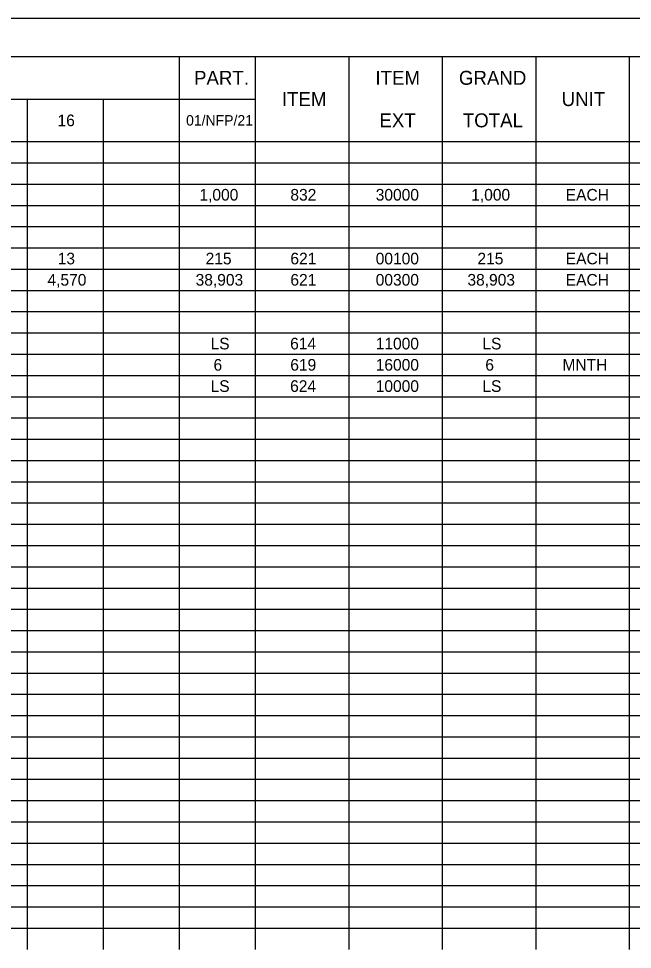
# Model space of a CAD drawing. Extents: x 0 to 34, y 0 to 22.
# Drawn here: x 8.4 to 16.49, y 9.74 to 22 of the extents above; entities that cross this region are included whole.
import ezdxf

# ---------------------------------------------------------------- set-up
doc = ezdxf.new("R2010")
doc.units = 0
for name, color, linetype in [('SH_Border', 7, 'Continuous'), ('SH_Cut_Line', 7, 'Continuous'), ('SH_Text', 7, 'Continuous')]:
    doc.layers.add(name, color=color, linetype=linetype)

msp = doc.modelspace()

# ---------------------------------------------------------------- linework, layer by layer
at = {"layer": 'SH_Border'}
msp.add_lwpolyline([(1.5, 21.5), (33.5, 21.5), (33.5, 0.5), (1.5, 0.5)], close=True, dxfattribs=at)
at = {"layer": 'SH_Cut_Line'}
msp.add_lwpolyline([(0, 0), (34, 0), (34, 22), (0, 22)], close=True, dxfattribs=at)
at = {"layer": 'SH_Text'}
for p, q in [((7.51, 21.5), (13.983, 21.5)), ((10.515, 21.5), (10.515, 21.22)), ((11.517, 21.5), (11.517, 21.22)), ((12.75, 21.5), (12.75, 21.22)), ((13.983, 21.5), (16.448, 21.5)), ((13.983, 21.5), (13.983, 21.22)), ((15.215, 21.5), (15.215, 21.22)), ((16.448, 21.5), (32, 21.5)), ((16.448, 21.5), (16.448, 21.22)), ((10.515, 21.22), (10.515, 20.94)), ((11.517, 21.22), (11.517, 20.94)), ((12.75, 21.22), (12.75, 20.94)), ((13.983, 21.22), (13.983, 20.94)), ((15.215, 21.22), (15.215, 20.94)), ((16.448, 21.22), (16.448, 20.94)), ((7.51, 20.94), (11.517, 20.94)), ((8.512, 20.94), (8.512, 20.66)), ((9.513, 20.94), (9.513, 20.66)), ((10.515, 20.94), (10.515, 20.66)), ((11.517, 20.94), (11.517, 20.66)), ((12.75, 20.94), (12.75, 20.66)), ((13.983, 20.94), (13.983, 20.66)), ((15.215, 20.94), (15.215, 20.66)), ((16.448, 20.94), (16.448, 20.66)), ((8.512, 20.66), (8.512, 20.38)), ((9.513, 20.66), (9.513, 20.38)), ((10.515, 20.66), (10.515, 20.38)), ((11.517, 20.66), (11.517, 20.38)), ((12.75, 20.66), (12.75, 20.38)), ((13.983, 20.66), (13.983, 20.38)), ((15.215, 20.66), (15.215, 20.38)), ((16.448, 20.66), (16.448, 20.38)), ((7.51, 20.38), (13.983, 20.38)), ((8.512, 20.38), (8.512, 20.1)), ((9.513, 20.38), (9.513, 20.1)), ((10.515, 20.38), (10.515, 20.1)), ((11.517, 20.38), (11.517, 20.1)), ((12.75, 20.38), (12.75, 20.1)), ((13.983, 20.38), (16.448, 20.38)), ((13.983, 20.38), (13.983, 20.1)), ((15.215, 20.38), (15.215, 20.1)), ((16.448, 20.38), (32, 20.38)), ((16.448, 20.38), (16.448, 20.1)), ((7.51, 20.1), (13.983, 20.1)), ((8.512, 20.1), (8.512, 18.7)), ((9.513, 20.1), (9.513, 18.7)), ((10.515, 20.1), (10.515, 18.7)), ((11.517, 20.1), (11.517, 18.7)), ((12.75, 20.1), (12.75, 18.7)), ((13.983, 20.1), (16.448, 20.1)), ((13.983, 20.1), (13.983, 18.7)), ((15.215, 20.1), (15.215, 18.7)), ((16.448, 20.1), (32, 20.1)), ((16.448, 20.1), (16.448, 18.7)), ((7.51, 19.82), (13.983, 19.82)), ((13.983, 19.82), (16.448, 19.82)), ((16.448, 19.82), (32, 19.82)), ((7.51, 19.54), (13.983, 19.54)), ((13.983, 19.54), (16.448, 19.54)), ((16.448, 19.54), (32, 19.54)), ((7.51, 19.26), (13.983, 19.26)), ((13.983, 19.26), (16.448, 19.26)), ((16.448, 19.26), (32, 19.26)), ((7.51, 18.98), (13.983, 18.98)), ((13.983, 18.98), (16.448, 18.98)), ((16.448, 18.98), (32, 18.98)), ((7.51, 18.7), (13.983, 18.7)), ((8.512, 18.7), (8.512, 18.14)), ((9.513, 18.7), (9.513, 18.14)), ((10.515, 18.7), (10.515, 18.14)), ((11.517, 18.7), (11.517, 18.14)), ((12.75, 18.7), (12.75, 18.14)), ((13.983, 18.7), (16.448, 18.7)), ((13.983, 18.7), (13.983, 18.14)), ((15.215, 18.7), (15.215, 18.14)), ((16.448, 18.7), (32, 18.7)), ((16.448, 18.7), (16.448, 18.14)), ((7.51, 18.42), (13.983, 18.42)), ((13.983, 18.42), (16.448, 18.42)), ((16.448, 18.42), (32, 18.42)), ((7.51, 18.14), (13.983, 18.14)), ((8.512, 18.14), (8.512, 17.86)), ((9.513, 18.14), (9.513, 17.86)), ((10.515, 18.14), (10.515, 17.86)), ((11.517, 18.14), (11.517, 17.86)), ((12.75, 18.14), (12.75, 17.86)), ((13.983, 18.14), (16.448, 18.14)), ((13.983, 18.14), (13.983, 17.86)), ((15.215, 18.14), (15.215, 17.86)), ((16.448, 18.14), (32, 18.14)), ((16.448, 18.14), (16.448, 17.86)), ((7.51, 17.86), (13.983, 17.86)), ((8.512, 17.86), (8.512, 17.58)), ((9.513, 17.86), (9.513, 17.58)), ((10.515, 17.86), (10.515, 17.58)), ((11.517, 17.86), (11.517, 17.58)), ((12.75, 17.86), (12.75, 17.58)), ((13.983, 17.86), (16.448, 17.86)), ((13.983, 17.86), (13.983, 17.58)), ((15.215, 17.86), (15.215, 17.58)), ((16.448, 17.86), (32, 17.86)), ((16.448, 17.86), (16.448, 17.58)), ((7.51, 17.58), (13.983, 17.58)), ((8.512, 17.58), (8.512, 17.3)), ((9.513, 17.58), (9.513, 17.3)), ((10.515, 17.58), (10.515, 17.3)), ((11.517, 17.58), (11.517, 17.3)), ((12.75, 17.58), (12.75, 17.3)), ((13.983, 17.58), (16.448, 17.58)), ((13.983, 17.58), (13.983, 17.3)), ((15.215, 17.58), (15.215, 17.3)), ((16.448, 17.58), (32, 17.58)), ((16.448, 17.58), (16.448, 17.3)), ((7.51, 17.3), (13.983, 17.3)), ((8.512, 17.3), (8.512, 17.02)), ((9.513, 17.3), (9.513, 17.02)), ((10.515, 17.3), (10.515, 17.02)), ((11.517, 17.3), (11.517, 17.02)), ((12.75, 17.3), (12.75, 17.02)), ((13.983, 17.3), (16.448, 17.3)), ((13.983, 17.3), (13.983, 17.02)), ((15.215, 17.3), (15.215, 17.02)), ((16.448, 17.3), (32, 17.3)), ((16.448, 17.3), (16.448, 17.02)), ((7.51, 17.02), (13.983, 17.02)), ((8.512, 17.02), (8.512, 16.74)), ((9.513, 17.02), (9.513, 16.74)), ((10.515, 17.02), (10.515, 16.74)), ((11.517, 17.02), (11.517, 16.74)), ((12.75, 17.02), (12.75, 16.74)), ((13.983, 17.02), (16.448, 17.02)), ((13.983, 17.02), (13.983, 16.74)), ((15.215, 17.02), (15.215, 16.74)), ((16.448, 17.02), (32, 17.02)), ((16.448, 17.02), (16.448, 16.74)), ((7.51, 16.74), (13.983, 16.74)), ((8.512, 16.74), (8.512, 16.18)), ((9.513, 16.74), (9.513, 16.18)), ((10.515, 16.74), (10.515, 16.18)), ((11.517, 16.74), (11.517, 16.18)), ((12.75, 16.74), (12.75, 16.18)), ((13.983, 16.74), (16.448, 16.74)), ((13.983, 16.74), (13.983, 16.18)), ((15.215, 16.74), (15.215, 16.18)), ((16.448, 16.74), (32, 16.74)), ((16.448, 16.74), (16.448, 16.18)), ((7.51, 16.46), (13.983, 16.46)), ((13.983, 16.46), (16.448, 16.46)), ((16.448, 16.46), (32, 16.46)), ((7.51, 16.18), (13.983, 16.18)), ((8.512, 16.18), (8.512, 15.9)), ((9.513, 16.18), (9.513, 15.9)), ((10.515, 16.18), (10.515, 15.9)), ((11.517, 16.18), (11.517, 15.9)), ((12.75, 16.18), (12.75, 15.9)), ((13.983, 16.18), (16.448, 16.18)), ((13.983, 16.18), (13.983, 15.9)), ((15.215, 16.18), (15.215, 15.9)), ((16.448, 16.18), (32, 16.18)), ((16.448, 16.18), (16.448, 15.9)), ((7.51, 15.9), (13.983, 15.9)), ((8.512, 15.9), (8.512, 15.62)), ((9.513, 15.9), (9.513, 15.62)), ((10.515, 15.9), (10.515, 15.62)), ((11.517, 15.9), (11.517, 15.62)), ((12.75, 15.9), (12.75, 15.62)), ((13.983, 15.9), (16.448, 15.9)), ((13.983, 15.9), (13.983, 15.62)), ((15.215, 15.9), (15.215, 15.62)), ((16.448, 15.9), (32, 15.9)), ((16.448, 15.9), (16.448, 15.62)), ((7.51, 15.62), (13.983, 15.62)), ((8.512, 15.62), (8.512, 15.34)), ((9.513, 15.62), (9.513, 15.34)), ((10.515, 15.62), (10.515, 15.34)), ((11.517, 15.62), (11.517, 15.34)), ((12.75, 15.62), (12.75, 15.34)), ((13.983, 15.62), (16.448, 15.62)), ((13.983, 15.62), (13.983, 15.34)), ((15.215, 15.62), (15.215, 15.34)), ((16.448, 15.62), (32, 15.62)), ((16.448, 15.62), (16.448, 15.34)), ((7.51, 15.34), (13.983, 15.34)), ((8.512, 15.34), (8.512, 14.78)), ((9.513, 15.34), (9.513, 14.78)), ((10.515, 15.34), (10.515, 14.78)), ((11.517, 15.34), (11.517, 14.78)), ((12.75, 15.34), (12.75, 14.78)), ((13.983, 15.34), (16.448, 15.34)), ((13.983, 15.34), (13.983, 14.78)), ((15.215, 15.34), (15.215, 14.78)), ((16.448, 15.34), (32, 15.34)), ((16.448, 15.34), (16.448, 14.78)), ((7.51, 15.06), (13.983, 15.06)), ((13.983, 15.06), (16.448, 15.06)), ((16.448, 15.06), (32, 15.06)), ((7.51, 14.78), (13.983, 14.78)), ((8.512, 14.78), (8.512, 14.5)), ((9.513, 14.78), (9.513, 14.5)), ((10.515, 14.78), (10.515, 14.5)), ((11.517, 14.78), (11.517, 14.5)), ((12.75, 14.78), (12.75, 14.5)), ((13.983, 14.78), (16.448, 14.78)), ((13.983, 14.78), (13.983, 14.5)), ((15.215, 14.78), (15.215, 14.5)), ((16.448, 14.78), (32, 14.78)), ((16.448, 14.78), (16.448, 14.5)), ((7.51, 14.5), (13.983, 14.5)), ((8.512, 14.5), (8.512, 14.22)), ((9.513, 14.5), (9.513, 14.22)), ((10.515, 14.5), (10.515, 14.22)), ((11.517, 14.5), (11.517, 14.22)), ((12.75, 14.5), (12.75, 14.22)), ((13.983, 14.5), (16.448, 14.5)), ((13.983, 14.5), (13.983, 14.22)), ((15.215, 14.5), (15.215, 14.22)), ((16.448, 14.5), (32, 14.5)), ((16.448, 14.5), (16.448, 14.22)), ((7.51, 14.22), (13.983, 14.22)), ((8.512, 14.22), (8.512, 13.94)), ((9.513, 14.22), (9.513, 13.94)), ((10.515, 14.22), (10.515, 13.94)), ((11.517, 14.22), (11.517, 13.94)), ((12.75, 14.22), (12.75, 13.94)), ((13.983, 14.22), (16.448, 14.22)), ((13.983, 14.22), (13.983, 13.94)), ((15.215, 14.22), (15.215, 13.94)), ((16.448, 14.22), (32, 14.22)), ((16.448, 14.22), (16.448, 13.94)), ((7.51, 13.94), (13.983, 13.94)), ((8.512, 13.94), (8.512, 11.7)), ((9.513, 13.94), (9.513, 11.7)), ((10.515, 13.94), (10.515, 11.7)), ((11.517, 13.94), (11.517, 11.7)), ((12.75, 13.94), (12.75, 11.7)), ((13.983, 13.94), (16.448, 13.94)), ((13.983, 13.94), (13.983, 11.7)), ((15.215, 13.94), (15.215, 11.7)), ((16.448, 13.94), (32, 13.94)), ((16.448, 13.94), (16.448, 11.7)), ((7.51, 13.66), (13.983, 13.66)), ((13.983, 13.66), (16.448, 13.66)), ((16.448, 13.66), (32, 13.66)), ((7.51, 13.38), (13.983, 13.38)), ((13.983, 13.38), (16.448, 13.38)), ((16.448, 13.38), (32, 13.38)), ((7.51, 13.1), (13.983, 13.1)), ((13.983, 13.1), (16.448, 13.1)), ((16.448, 13.1), (32, 13.1)), ((7.51, 12.82), (13.983, 12.82)), ((13.983, 12.82), (16.448, 12.82)), ((16.448, 12.82), (32, 12.82)), ((7.51, 12.54), (13.983, 12.54)), ((13.983, 12.54), (16.448, 12.54)), ((16.448, 12.54), (32, 12.54)), ((7.51, 12.26), (13.983, 12.26)), ((13.983, 12.26), (16.448, 12.26)), ((16.448, 12.26), (32, 12.26)), ((7.51, 11.98), (13.983, 11.98)), ((13.983, 11.98), (16.448, 11.98)), ((16.448, 11.98), (32, 11.98)), ((7.51, 11.7), (13.983, 11.7)), ((8.512, 11.7), (8.512, 11.42)), ((9.513, 11.7), (9.513, 11.42)), ((10.515, 11.7), (10.515, 11.42)), ((11.517, 11.7), (11.517, 11.42)), ((12.75, 11.7), (12.75, 11.42)), ((13.983, 11.7), (16.448, 11.7)), ((13.983, 11.7), (13.983, 11.42)), ((15.215, 11.7), (15.215, 11.42)), ((16.448, 11.7), (32, 11.7)), ((16.448, 11.7), (16.448, 11.42)), ((7.51, 11.42), (13.983, 11.42)), ((8.512, 11.42), (8.512, 10.3)), ((9.513, 11.42), (9.513, 10.3)), ((10.515, 11.42), (10.515, 10.3)), ((11.517, 11.42), (11.517, 10.3)), ((12.75, 11.42), (12.75, 10.3)), ((13.983, 11.42), (16.448, 11.42)), ((13.983, 11.42), (13.983, 10.3)), ((15.215, 11.42), (15.215, 10.3)), ((16.448, 11.42), (32, 11.42)), ((16.448, 11.42), (16.448, 10.3)), ((7.51, 11.14), (13.983, 11.14)), ((13.983, 11.14), (16.448, 11.14)), ((16.448, 11.14), (32, 11.14)), ((7.51, 10.86), (13.983, 10.86)), ((13.983, 10.86), (16.448, 10.86)), ((16.448, 10.86), (32, 10.86)), ((7.51, 10.58), (13.983, 10.58)), ((13.983, 10.58), (16.448, 10.58)), ((16.448, 10.58), (32, 10.58)), ((7.51, 10.3), (13.983, 10.3)), ((8.512, 10.3), (8.512, 10.02)), ((9.513, 10.3), (9.513, 10.02)), ((10.515, 10.3), (10.515, 10.02)), ((11.517, 10.3), (11.517, 10.02)), ((12.75, 10.3), (12.75, 10.02)), ((13.983, 10.3), (16.448, 10.3)), ((13.983, 10.3), (13.983, 10.02)), ((15.215, 10.3), (15.215, 10.02)), ((16.448, 10.3), (32, 10.3)), ((16.448, 10.3), (16.448, 10.02)), ((7.51, 10.02), (13.983, 10.02)), ((8.512, 10.02), (8.512, 9.74)), ((9.513, 10.02), (9.513, 9.74)), ((10.515, 10.02), (10.515, 9.74)), ((11.517, 10.02), (11.517, 9.74)), ((12.75, 10.02), (12.75, 9.74)), ((13.983, 10.02), (16.448, 10.02)), ((13.983, 10.02), (13.983, 9.74)), ((15.215, 10.02), (15.215, 9.74)), ((16.448, 10.02), (32, 10.02)), ((16.448, 10.02), (16.448, 9.74))]:
    msp.add_line(p, q, dxfattribs=at)

# ---------------------------------------------------------------- texts
for s, height, p in [('PART.', 0.184, (10.71, 21.128)), ('ITEM', 0.184, (13.101, 21.128)), ('GRAND', 0.184, (14.202, 21.128)), ('ITEM', 0.184, (11.868, 20.848)), ('UNIT', 0.184, (15.556, 20.848)), ('16', 0.1533, (8.911, 20.583)), ('01/NFP/21', 0.138, (10.605, 20.591)), ('EXT', 0.184, (13.154, 20.568)), ('TOTAL', 0.184, (14.253, 20.568)), ('1,000', 0.1533, (10.781, 19.603)), ('832', 0.1533, (11.98, 19.603)), ('30000', 0.1533, (13.105, 19.603)), ('1,000', 0.1533, (14.364, 19.603)), ('EACH', 0.1533, (15.61, 19.603)), ('13', 0.1533, (8.913, 18.763)), ('215', 0.1533, (10.863, 18.763)), ('621', 0.1533, (11.98, 18.763)), ('00100', 0.1533, (13.105, 18.763)), ('215', 0.1533, (14.446, 18.763)), ('EACH', 0.1533, (15.61, 18.763)), ('4,570', 0.1533, (8.778, 18.483)), ('38,903', 0.1533, (10.731, 18.483)), ('621', 0.1533, (11.98, 18.483)), ('00300', 0.1533, (13.105, 18.483)), ('38,903', 0.1533, (14.314, 18.483)), ('EACH', 0.1533, (15.61, 18.483)), ('LS', 0.1533, (10.928, 17.643)), ('614', 0.1533, (11.977, 17.643)), ('11000', 0.1533, (13.105, 17.643)), ('LS', 0.1533, (14.511, 17.643)), ('6', 0.153, (10.967, 17.363)), ('619', 0.1533, (11.979, 17.363)), ('16000', 0.1533, (13.105, 17.363)), ('6', 0.153, (14.55, 17.363)), ('MNTH', 0.1533, (15.567, 17.363)), ('LS', 0.1533, (10.928, 17.083)), ('624', 0.1533, (11.977, 17.083)), ('10000', 0.1533, (13.105, 17.083)), ('LS', 0.1533, (14.511, 17.083))]:
    msp.add_text(s, height=height, dxfattribs=at).set_placement(p)

doc.saveas('drawing.dxf')
